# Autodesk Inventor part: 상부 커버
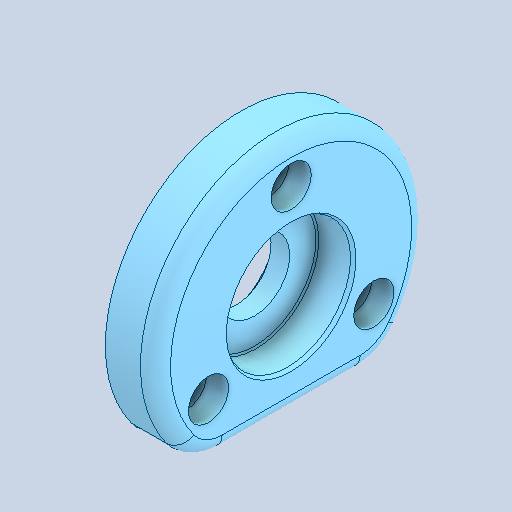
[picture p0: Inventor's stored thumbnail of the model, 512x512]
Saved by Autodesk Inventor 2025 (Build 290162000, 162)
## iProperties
Created: 2026-07
Part Number: 상부 커버
Material: 일반
Document SubType Name: Modeling
Designer: KDI
Density: 1 g/cm^3
Appearance: 기본값
Author: jhkim
Sending System: Autodesk Inventor 2027
Preprocessor: ST-DEVELOPER v20.1
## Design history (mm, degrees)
feature "솔리드1"
node "솔리드2"
